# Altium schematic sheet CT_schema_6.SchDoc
size 371 x 245 mm
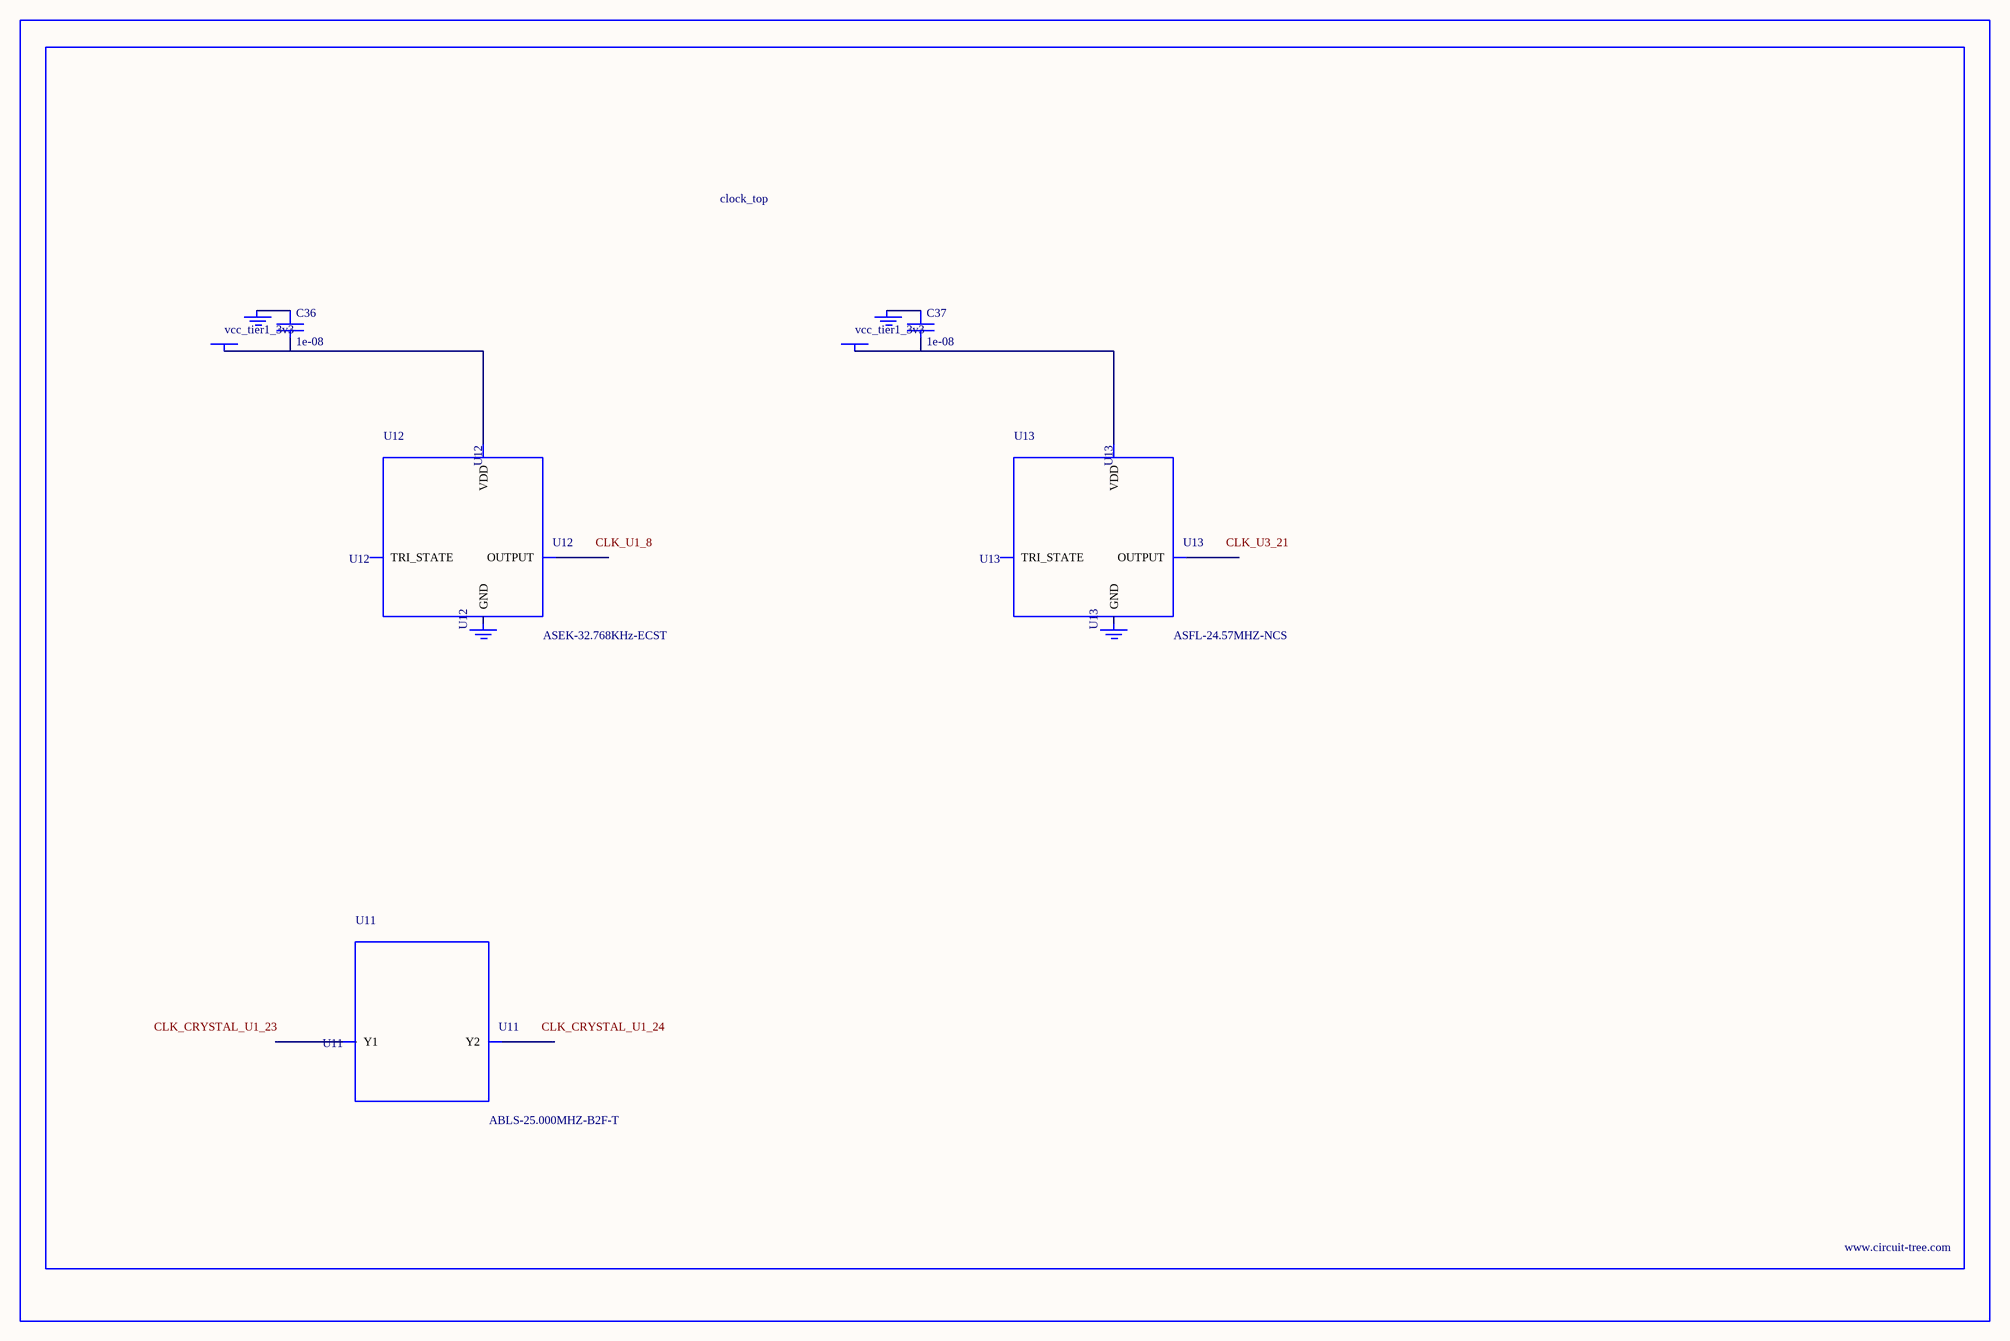
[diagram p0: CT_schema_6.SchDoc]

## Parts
BORDER5  (no value)
C36  1e-08  [C0402]
C37  1e-08  [C0402]
GND_INSTANCE_5_0  (no value)
GND_INSTANCE_5_1  (no value)
GND_INSTANCE_5_2  (no value)
GND_INSTANCE_5_3  (no value)
POWER_INSTANCE_5_0  vcc_tier1_3v3
POWER_INSTANCE_5_1  vcc_tier1_3v3
U11  ABLS-25.000MHZ-B2F-T  [ABLS-25.000MHZ-B2F-T]
U12  ASEK-32.768KHz-ECST  [ASEK]
U13  ASFL-24.57MHZ-NCS  [ASFL1]

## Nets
NetC36_1: C36.1 GND_INSTANCE_5_0.0(GND)
NetC36_2: C36.2 POWER_INSTANCE_5_0.0(PWR) U12.4(VDD)
NetC37_1: C37.1 GND_INSTANCE_5_2.0(GND)
NetC37_2: C37.2 POWER_INSTANCE_5_1.0(PWR) U13.4(VDD)

Not connected (* = marked no-connect by the designer): GND_INSTANCE_5_1 0(GND); GND_INSTANCE_5_3 0(GND); U11 1(Y1) 2(Y2); U12 1(TRI_STATE) 2(GND) 3(OUTPUT); U13 1(TRI_STATE) 2(GND) 3(OUTPUT)

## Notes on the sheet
- Labels drawn without touching a wire or pin: CLK_CRYSTAL_U1_23, CLK_CRYSTAL_U1_24, CLK_U1_8, CLK_U3_21

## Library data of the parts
BORDER5 = BORDER_PAGE5
C36 C37 = C0402C103K3RAC
GND_INSTANCE_5_0-GND_INSTANCE_5_3 = GND
POWER_INSTANCE_5_0 POWER_INSTANCE_5_1 = PWR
